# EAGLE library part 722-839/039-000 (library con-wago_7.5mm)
Serie 722, Federleiste mit Verriegelungsklinken / Series 722, Female connector with locking levers Polzahl / Pole No.: 9 Farbe / Color: lichtgrau / light gray Stand: 01.01.2012. Die jeweils aktuellen Daten zu diesem Artikel finden Sie in unserem Produktkatalog, den Sie unter www.wago.com einsehen können. As of: 01/01/2012. Please find the newest data for this article in our product catalogue, which can be viewed under www.wago.com.
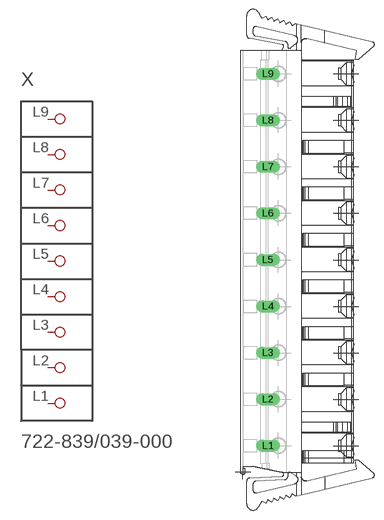
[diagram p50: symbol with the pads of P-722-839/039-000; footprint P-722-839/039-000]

Designator prefix X

## 722-839/039-000  [P-722-839/039-000]
L1  P1
L2  P2
L3  P3
L4  P4
L5  P5
L6  P6
L7  P7
L8  P8
L9  P9

## Footprint P-722-839/039-000 (pad centres in mm)
drill 1.3 long: L1 -5.982,-30; L2 -5.982,-22.5; L3 -5.982,-15; L4 -5.982,-7.5; L5 -5.982,0; L6 -5.982,7.5; L7 -5.982,15; L8 -5.982,22.5; L9 -5.982,30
